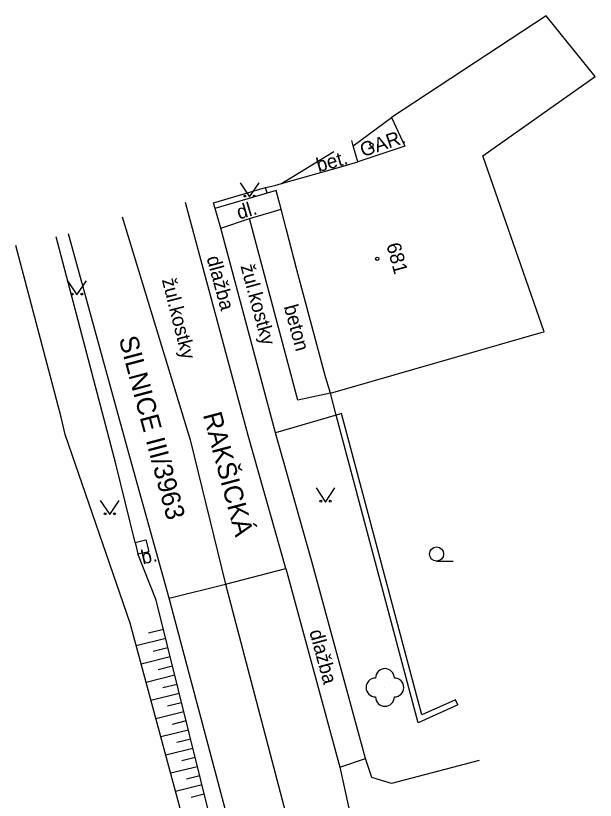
# Model space of a CAD drawing. Extents: x -621335 to -621199, y -1175437 to -1175180.
# Drawn here: x -621334.74 to -621303.99, y -1175221.43 to -1175179.79 of the extents above; entities that cross this region are included whole.
import ezdxf

# ---------------------------------------------------------------- set-up
doc = ezdxf.new("R2010")
doc.units = 0
for name, color, linetype in [('Budovy - měřené', 7, 'Continuous'), ('Budovy - zadní trakty', 7, 'Continuous'), ('Doplňkové značky', 7, 'Continuous'), ('Názvy', 7, 'Continuous'), ('Pomocné popisy', 7, 'Continuous'), ('Rozhraní ploch', 7, 'Continuous'), ('Výškopis', 7, 'Continuous'), ('Zeleň', 7, 'Continuous'), ('Značky druhů budov', 7, 'Continuous'), ('Značky kultur', 7, 'Continuous'), ('Čísla popisná_evidenční', 7, 'Continuous')]:
    doc.layers.add(name, color=color, linetype=linetype)

msp = doc.modelspace()

# ---------------------------------------------------------------- linework, layer by layer
at = {"layer": 'Budovy - měřené'}
for p, q in [((-621316.59, -1175187.55), (-621316.83, -1175186.7)), ((-621320.37, -1175191.16), (-621320.66, -1175190.06))]:
    msp.add_line(p, q, dxfattribs=at)
for points in [[(-621320.93, -1175189.07), (-621321.4, -1175189.2), (-621321.48, -1175188.91), (-621321, -1175188.8), (-621320.64, -1175188.7), (-621317.36, -1175187.77), (-621316.59, -1175187.55)], [(-621318.03, -1175199.82), (-621318.3, -1175198.96), (-621319.82, -1175193.27)]]:
    msp.add_lwpolyline(points, dxfattribs=at)
at = {"layer": 'Budovy - zadní trakty'}
msp.add_line((-621316.83, -1175186.7), (-621314.8, -1175185.2), dxfattribs=at)
msp.add_lwpolyline([(-621318.03, -1175199.82), (-621306.86, -1175196.61), (-621306.71, -1175196.57), (-621309.96, -1175187.22), (-621303.99, -1175183.02), (-621306.59, -1175179.79), (-621314.8, -1175185.2), (-621314.09, -1175186.71), (-621316.59, -1175187.55)], dxfattribs=at)
at = {"layer": 'Doplňkové značky'}
for p, q in [((-621316.83, -1175186.7), (-621316.91, -1175186.41)), ((-621320.66, -1175190.06), (-621320.93, -1175189.07)), ((-621319.82, -1175193.27), (-621320.37, -1175191.16)), ((-621317.74, -1175200.99), (-621318.03, -1175199.82)), ((-621317.45, -1175200.91), (-621317.74, -1175200.99)), ((-621311.28, -1175216.37), (-621311.4, -1175216.1))]:
    msp.add_line(p, q, dxfattribs=at)
for points in [[(-621323.13, -1175232.55), (-621328.67, -1175212.03), (-621332.12, -1175202.01), (-621332.33, -1175201.1), (-621334.74, -1175191.98)], [(-621311.28, -1175216.37), (-621313.39, -1175217.31), (-621317.74, -1175200.99)], [(-621311.4, -1175216.1), (-621313.191, -1175216.893), (-621317.45, -1175200.91)]]:
    msp.add_lwpolyline(points, dxfattribs=at)
at = {"layer": 'Rozhraní ploch'}
for p, q in [((-621320.64, -1175188.7), (-621317.87, -1175187)), ((-621321.4, -1175189.2), (-621324.17, -1175190.02)), ((-621323.86, -1175191.07), (-621324.25, -1175189.73)), ((-621320.95, -1175201.92), (-621323.86, -1175191.07)), ((-621317.74, -1175200.99), (-621320.95, -1175201.92)), ((-621328.4, -1175207.74), (-621327.83, -1175207.61)), ((-621327.83, -1175207.61), (-621327.67, -1175208.22)), ((-621328.4, -1175207.74), (-621328.26, -1175208.35)), ((-621328.26, -1175208.35), (-621327.67, -1175208.22)), ((-621320.41, -1175209.12), (-621317.54, -1175219.67)), ((-621323.61, -1175209.95), (-621318.1, -1175230.88)), ((-621321, -1175231.78), (-621326.59, -1175210.7)), ((-621317.54, -1175219.67), (-621316.19, -1175219.21)), ((-621317.54, -1175219.67), (-621315.3, -1175229.97))]:
    msp.add_line(p, q, dxfattribs=at)
for points in [[(-621320.41, -1175209.12), (-621322.41, -1175202.07), (-621325.73, -1175189.7)], [(-621323.86, -1175191.07), (-621322.33, -1175190.56), (-621321.18, -1175190.21), (-621320.66, -1175190.06)], [(-621329.09, -1175190.47), (-621325.49, -1175202.3), (-621323.61, -1175209.95)], [(-621318.03, -1175199.82), (-621319.77, -1175200.19), (-621322.33, -1175190.56)], [(-621326.59, -1175210.7), (-621328.66, -1175203.27), (-621331.93, -1175191.36)], [(-621316.19, -1175219.21), (-621319.03, -1175208.75), (-621320.95, -1175201.92)], [(-621326.59, -1175210.7), (-621323.61, -1175209.95), (-621320.41, -1175209.12)], [(-621310.16, -1175219.31), (-621314.8, -1175220.54), (-621315.84, -1175220.22), (-621316.19, -1175219.21)]]:
    msp.add_lwpolyline(points, dxfattribs=at)
at = {"layer": 'Výškopis'}
for p, q in [((-621326.904, -1175212.365), (-621327.689, -1175212.56)), ((-621326.783, -1175212.85), (-621328.344, -1175213.238)), ((-621326.662, -1175213.335), (-621327.438, -1175213.528)), ((-621326.542, -1175213.821), (-621328.083, -1175214.204)), ((-621326.421, -1175214.306), (-621327.187, -1175214.496)), ((-621326.301, -1175214.791), (-621327.822, -1175215.169)), ((-621326.18, -1175215.276), (-621326.936, -1175215.464)), ((-621326.06, -1175215.762), (-621327.562, -1175216.135)), ((-621325.939, -1175216.247), (-621326.685, -1175216.432)), ((-621325.818, -1175216.732), (-621327.301, -1175217.101)), ((-621325.698, -1175217.217), (-621326.434, -1175217.4)), ((-621325.577, -1175217.703), (-621327.04, -1175218.066)), ((-621325.457, -1175218.188), (-621326.183, -1175218.368)), ((-621325.336, -1175218.673), (-621326.78, -1175219.032)), ((-621325.216, -1175219.158), (-621325.932, -1175219.337)), ((-621325.095, -1175219.644), (-621326.519, -1175219.997)), ((-621324.974, -1175220.129), (-621325.681, -1175220.305)), ((-621324.854, -1175220.614), (-621326.258, -1175220.963)), ((-621324.733, -1175221.099), (-621325.431, -1175221.273))]:
    msp.add_line(p, q, dxfattribs=at)
for points in [[(-621328.4, -1175207.74), (-621329.42, -1175203.57), (-621332.6, -1175191.53)], [(-621321.96, -1175232.26), (-621327.29, -1175210.81), (-621328.26, -1175208.35)]]:
    msp.add_lwpolyline(points, dxfattribs=at)
at = {"layer": 'Zeleň'}
msp.add_line((-621324.25, -1175189.73), (-621321.48, -1175188.91), dxfattribs=at)
msp.add_circle((-621315.15, -1175215.44), 0.0005, dxfattribs=at)
for centre, start, end in [((-621315.15, -1175214.94), 0, 180), ((-621315.65, -1175215.44), 90, 270), ((-621314.65, -1175215.44), 270, 90), ((-621315.15, -1175215.94), 180, 360)]:
    msp.add_arc(centre, 0.5, start, end, dxfattribs=at)
at = {"layer": 'Značky druhů budov'}
for centre in [(-621315.86, -1175186.65), (-621315.56, -1175192.69)]:
    msp.add_circle(centre, 0.0875, dxfattribs=at)
at = {"layer": 'Značky kultur'}
msp.add_line((-621312.41, -1175208.735), (-621311.535, -1175208.735), dxfattribs=at)
for points in [[(-621322.83, -1175188.66), (-621322.33, -1175189.41), (-621321.83, -1175188.66)], [(-621331.99, -1175193.86), (-621331.49, -1175194.61), (-621330.99, -1175193.86)], [(-621318.8, -1175204.85), (-621318.3, -1175205.6), (-621317.8, -1175204.85)], [(-621330.25, -1175205.52), (-621329.75, -1175206.27), (-621329.25, -1175205.52)]]:
    msp.add_lwpolyline(points, dxfattribs=at)
for centre, radius in [((-621322.58, -1175189.36), 0.05), ((-621322.08, -1175189.36), 0.05), ((-621331.74, -1175194.56), 0.05), ((-621331.24, -1175194.56), 0.05), ((-621318.55, -1175205.55), 0.05), ((-621318.05, -1175205.55), 0.05), ((-621330, -1175206.22), 0.05), ((-621329.5, -1175206.22), 0.05), ((-621312.41, -1175208.36), 0.375)]:
    msp.add_circle(centre, radius, dxfattribs=at)

# ---------------------------------------------------------------- texts
at = {"layer": 'Názvy'}
for s, p in [('SILNICE III/3963', (-621329.276, -1175196.927)), ('RAKŠICKÁ', (-621324.815, -1175200.966))]:
    msp.add_text(s, height=1, rotation=284.9108, dxfattribs=at).set_placement(p)
at = {"layer": 'Pomocné popisy'}
for s, rotation, p in [('GAR.', 18.57, (-621316.32, -1175187.3)), ('bet.', 15.7998, (-621318.67, -1175188.1)), ('dl.', 16.49, (-621322.89, -1175190.61)), ('dlažba', 285.2183, (-621324.62, -1175192.64)), ('žul.kostky', 285.2183, (-621322.82, -1175193.08)), ('žul.kostky', 284.29, (-621326.99, -1175193.81)), ('beton', 285.2183, (-621320.52, -1175195.23)), ('b.', 12.8477, (-621327.996, -1175208.915)), ('dlažba', 285.2183, (-621319.17, -1175212.47))]:
    msp.add_text(s, height=0.75, rotation=rotation, dxfattribs=at).set_placement(p)
at = {"layer": 'Čísla popisná_evidenční'}
msp.add_text('681', height=0.75, rotation=285.31, dxfattribs=at).set_placement((-621315.08, -1175191.95))

doc.saveas('drawing.dxf')
